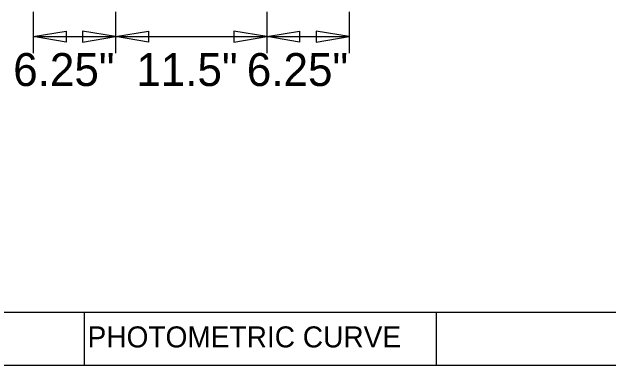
# Model space of a CAD drawing. Extents: x 17890628 to 17890754, y 17897693 to 17897992.
# Drawn here: x 17890699.549 to 17890703.321, y 17897882.404 to 17897884.638 of the extents above; entities that cross this region are included whole.
import ezdxf

# ---------------------------------------------------------------- set-up
doc = ezdxf.new("R2010")
doc.units = 0
for name, color, linetype in [('GSDims', 7, 'Continuous'), ('SheetLinesMisc2_dp', 7, 'Continuous'), ('TextMinor', 7, 'Continuous')]:
    doc.layers.add(name, color=color, linetype=linetype)

msp = doc.modelspace()

# ---------------------------------------------------------------- linework, layer by layer
at = {"layer": 'GSDims'}
for p, q in [((17890699.6828, 17897884.6383), (17890699.6828, 17897884.3778)), ((17890699.6828, 17897884.6383), (17890699.6828, 17897884.3778)), ((17890700.2045, 17897884.6383), (17890700.2045, 17897884.3778)), ((17890700.2045, 17897884.6383), (17890700.2045, 17897884.3778)), ((17890701.1612, 17897884.6383), (17890701.1612, 17897884.3778)), ((17890701.1612, 17897884.6383), (17890701.1612, 17897884.3778)), ((17890701.6828, 17897884.6383), (17890701.6828, 17897884.3778)), ((17890701.6828, 17897884.6383), (17890701.6828, 17897884.3778)), ((17890699.6828, 17897884.482), (17890700.2045, 17897884.482)), ((17890700.2045, 17897884.482), (17890701.1612, 17897884.482)), ((17890701.1612, 17897884.482), (17890701.6828, 17897884.482))]:
    msp.add_line(p, q, dxfattribs=at)
for points in [[(17890699.6828, 17897884.482), (17890699.8911, 17897884.5167), (17890699.8911, 17897884.4473)], [(17890700.2045, 17897884.482), (17890699.9962, 17897884.5167), (17890699.9962, 17897884.4473)], [(17890700.2045, 17897884.482), (17890700.4128, 17897884.5167), (17890700.4128, 17897884.4473)], [(17890701.1612, 17897884.482), (17890700.9528, 17897884.5167), (17890700.9528, 17897884.4473)], [(17890701.1612, 17897884.482), (17890701.3695, 17897884.5167), (17890701.3695, 17897884.4473)], [(17890701.6828, 17897884.482), (17890701.4745, 17897884.5167), (17890701.4745, 17897884.4473)]]:
    msp.add_lwpolyline(points, close=True, dxfattribs=at)
at = {"layer": 'SheetLinesMisc2_dp'}
for p, q in [((17890694.3026, 17897882.7378), (17890707.0939, 17897882.7378)), ((17890700.0064, 17897882.7378), (17890700.0064, 17897882.4039)), ((17890702.2334, 17897882.7378), (17890702.2334, 17897882.4039)), ((17890694.3026, 17897882.4039), (17890707.0939, 17897882.4039))]:
    msp.add_line(p, q, dxfattribs=at)

# ---------------------------------------------------------------- texts
at = {"layer": 'GSDims'}
for s, p in [('6.25"', (17890699.5567, 17897884.1695)), ('11.5"', (17890700.3356, 17897884.1695)), ('6.25"', (17890701.0351, 17897884.1695))]:
    msp.add_text(s, height=0.20833, dxfattribs=at).set_placement(p)
at = {"layer": 'TextMinor'}
msp.add_text('PHOTOMETRIC CURVE', height=0.132863, dxfattribs=at).set_placement((17890700.0274, 17897882.5157))

doc.saveas('drawing.dxf')
